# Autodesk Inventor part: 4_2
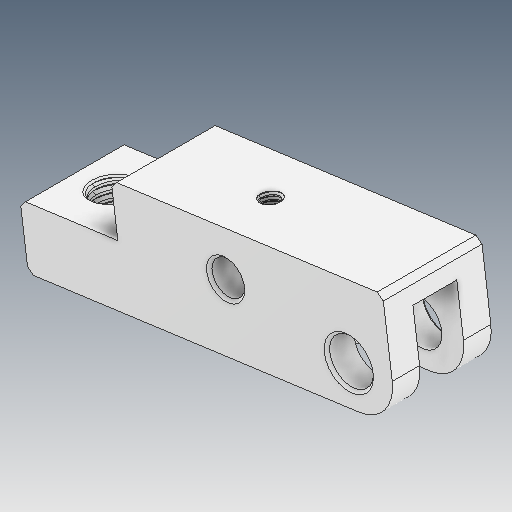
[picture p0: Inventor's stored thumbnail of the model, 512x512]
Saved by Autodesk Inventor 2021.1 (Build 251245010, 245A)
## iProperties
Created: 2021-06
Part Number: 4_2
Material: Ogólny
Document SubType Name: Modeling
Designer: user
Density: 1 g/cm^3
Appearance: Domyślna
Author: user
Revision Number: ÈÎºÎ
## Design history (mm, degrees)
feature "ÊäÈë1"
node "Bryła1"
